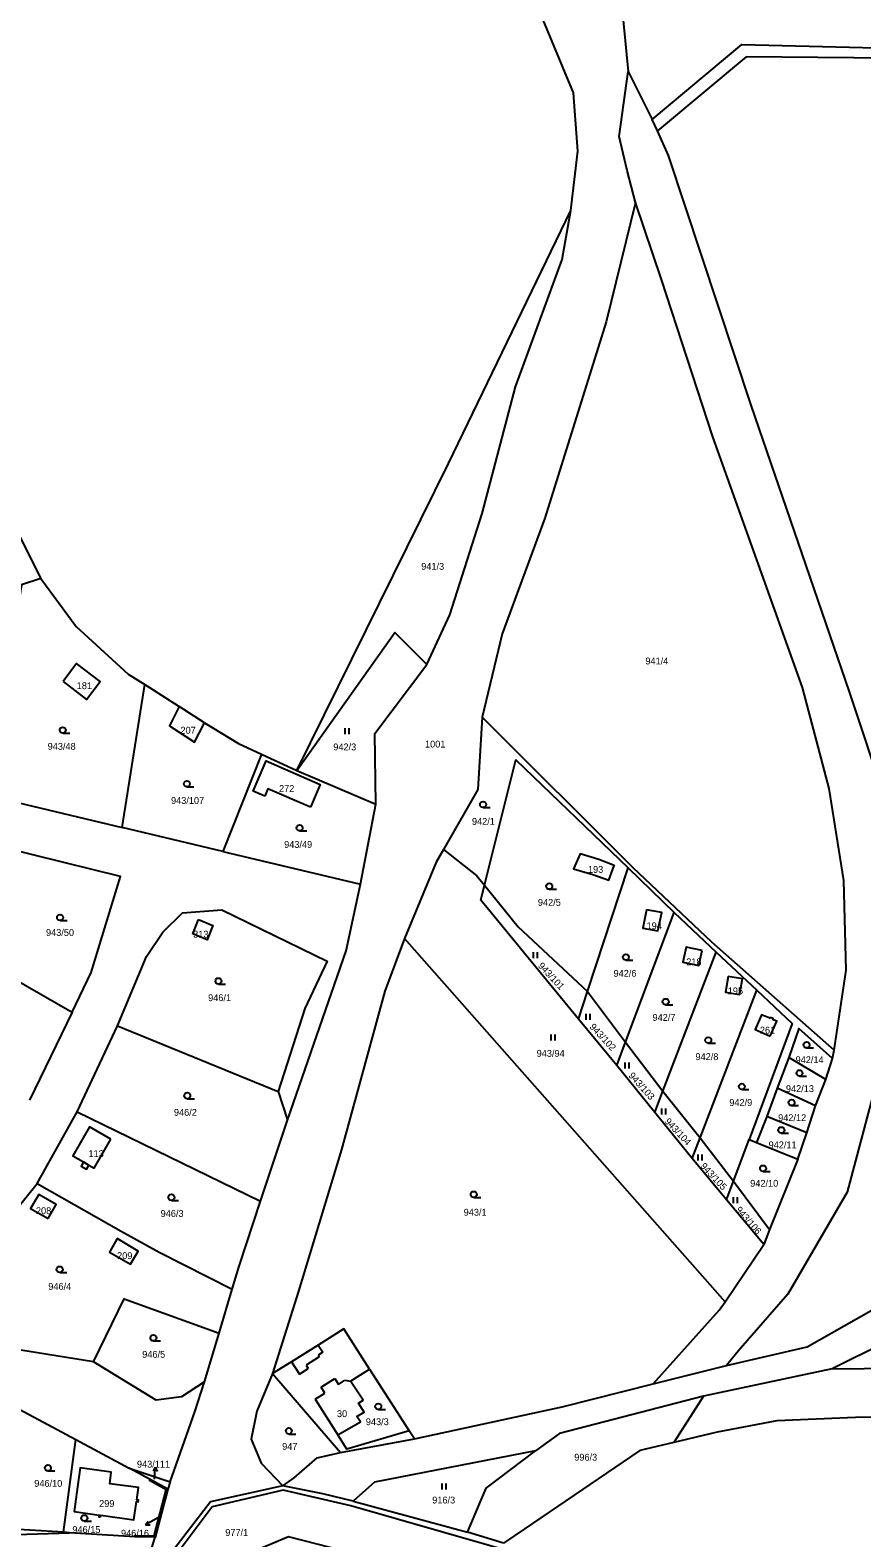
# Model space of a CAD drawing. Extents: x -7483133 to -743907, y -11317770 to -1129777.
# Drawn here: x -750645.6 to -750439.3, y -1131231.7 to -1130857.7 of the extents above; entities that cross this region are included whole.
import ezdxf

# ---------------------------------------------------------------- set-up
doc = ezdxf.new("R2010")
doc.units = 0
for name, color, linetype in [('Hranice parcel', 7, 'Continuous'), ('Parcelní čísla', 7, 'Continuous'), ('Pop  PČ popisy', 7, 'Continuous'), ('Vnitřní kresba', 7, 'Continuous'), ('Značky kultur', 7, 'Continuous')]:
    doc.layers.add(name, color=color, linetype=linetype)

msp = doc.modelspace()

# ---------------------------------------------------------------- linework, layer by layer
at = {"layer": 'Hranice parcel'}
for p, q in [((-750497.26, -1130867.97), (-750491.25, -1130879.86)), ((-750489.98, -1130882.7), (-750491.25, -1130879.86)), ((-750653.79, -1130972.43), (-750642.94, -1130993.73)), ((-750622.78, -1131055.54), (-750617.17, -1131020.08)), ((-750617.17, -1131020.08), (-750608.62, -1131025.49)), ((-750602.38, -1131029.51), (-750608.62, -1131025.49)), ((-750588.24, -1131037.32), (-750597.78, -1131061.49)), ((-750588.24, -1131037.32), (-750579.43, -1131041.4)), ((-750579.43, -1131041.4), (-750559.85, -1131049.76)), ((-750563.69, -1131069.55), (-750559.85, -1131049.76)), ((-750597.78, -1131061.49), (-750622.78, -1131055.54)), ((-750597.78, -1131061.49), (-750563.69, -1131069.55)), ((-750507.32, -1131096.22), (-750497.27, -1131065.52)), ((-750497.27, -1131065.52), (-750485.87, -1131076.56)), ((-750497.91, -1131108.74), (-750485.87, -1131076.56)), ((-750485.87, -1131076.56), (-750475.37, -1131086.44)), ((-750473.19, -1131173.15), (-750552.77, -1131083.07)), ((-750658.73, -1131087.82), (-750635.2, -1131101.36)), ((-750488.61, -1131120.96), (-750475.37, -1131086.44)), ((-750475.37, -1131086.44), (-750465.29, -1131095.85)), ((-750509.57, -1131103.09), (-750507.32, -1131096.22)), ((-750507.32, -1131096.22), (-750497.91, -1131108.74)), ((-750479.38, -1131132.47), (-750465.29, -1131095.85)), ((-750635.2, -1131101.36), (-750645.75, -1131123.19)), ((-750633.92, -1131126.08), (-750623.98, -1131104.75)), ((-750623.98, -1131104.75), (-750584.08, -1131121.02)), ((-750500.08, -1131114.54), (-750509.57, -1131103.09)), ((-750500.08, -1131114.54), (-750497.91, -1131108.74)), ((-750497.91, -1131108.74), (-750488.61, -1131120.96)), ((-750457.41, -1131112.56), (-750460.24, -1131120.18)), ((-750448.23, -1131118.01), (-750457.41, -1131112.56)), ((-750448.23, -1131118.01), (-750446.53, -1131112.81)), ((-750446.53, -1131112.81), (-750446.13, -1131110.72)), ((-750490.63, -1131126.23), (-750500.08, -1131114.54)), ((-750584.08, -1131121.02), (-750581.77, -1131128.11)), ((-750490.63, -1131126.23), (-750488.61, -1131120.96)), ((-750488.61, -1131120.96), (-750479.38, -1131132.47)), ((-750460.24, -1131120.18), (-750462.82, -1131127.24)), ((-750450.77, -1131124.56), (-750460.24, -1131120.18)), ((-750450.77, -1131124.56), (-750448.23, -1131118.01)), ((-750452.87, -1131131.28), (-750450.77, -1131124.56)), ((-750643.85, -1131143.83), (-750633.92, -1131126.08)), ((-750633.92, -1131126.08), (-750588.48, -1131148.2)), ((-750588.48, -1131148.2), (-750581.77, -1131128.11)), ((-750481.37, -1131137.63), (-750490.63, -1131126.23)), ((-750462.82, -1131127.24), (-750465.37, -1131133.64)), ((-750452.87, -1131131.28), (-750462.82, -1131127.24)), ((-750481.37, -1131137.63), (-750479.38, -1131132.47)), ((-750479.38, -1131132.47), (-750471.07, -1131143.22)), ((-750455.14, -1131137.79), (-750452.87, -1131131.28)), ((-750471.07, -1131143.22), (-750467.23, -1131132.9)), ((-750467.23, -1131132.9), (-750465.37, -1131133.64)), ((-750465.37, -1131133.64), (-750455.14, -1131137.79)), ((-750472.81, -1131147.91), (-750481.37, -1131137.63)), ((-750455.14, -1131137.79), (-750462.15, -1131155.21)), ((-750472.81, -1131147.91), (-750471.07, -1131143.22)), ((-750471.07, -1131143.22), (-750462.15, -1131155.21)), ((-750463.62, -1131158.93), (-750472.81, -1131147.91)), ((-750473.19, -1131173.15), (-750463.62, -1131158.93)), ((-750598.74, -1131180.95), (-750595.5, -1131170.04)), ((-750602.36, -1131193.01), (-750598.74, -1131180.95)), ((-750580.75, -1131188.08), (-750585.52, -1131190.95)), ((-750446.64, -1131189.81), (-750338.88, -1131188.45)), ((-750663.9, -1131191.45), (-750634.31, -1131207.35)), ((-750585.52, -1131190.95), (-750568.64, -1131210.54)), ((-750566.12, -1131192.88), (-750561.42, -1131189.86)), ((-750561.42, -1131189.86), (-750551.57, -1131205.21)), ((-750491, -1131193.51), (-750472.83, -1131188.97)), ((-750446.64, -1131189.81), (-750478.58, -1131196.61)), ((-750478.58, -1131196.61), (-750485.93, -1131208.1)), ((-750637.34, -1131230.32), (-750634.31, -1131207.35)), ((-750634.31, -1131207.35), (-750621.05, -1131214.47)), ((-750568.64, -1131210.54), (-750550.24, -1131207.13)), ((-750550.24, -1131207.13), (-750551.57, -1131205.21)), ((-750615.88, -1131217.25), (-750621.05, -1131214.47)), ((-750621.05, -1131214.47), (-750610.86, -1131217.83)), ((-750611.5, -1131219.65), (-750615.88, -1131217.25)), ((-750610.86, -1131217.83), (-750611.5, -1131219.65)), ((-750611.5, -1131219.65), (-750614.64, -1131231.58)), ((-750565.51, -1131222.62), (-750537.12, -1131230.36)), ((-750637.34, -1131230.32), (-750676.72, -1131228.08)), ((-750635.87, -1131230.45), (-750637.34, -1131230.32)), ((-750619.64, -1131231.48), (-750635.87, -1131230.45)), ((-750614.64, -1131231.58), (-750619.64, -1131231.48)), ((-750617.63, -1131241.09), (-750614.64, -1131231.58)), ((-750528.14, -1131233.04), (-750537.12, -1131230.36))]:
    msp.add_line(p, q, dxfattribs=at)
for points in [[(-750522.68, -1130780.11), (-750499.63, -1130847.01), (-750499.12, -1130848.49), (-750497.26, -1130867.97)], [(-750511.43, -1130902.47), (-750509.76, -1130887.71), (-750510.81, -1130873.25), (-750518.73, -1130854.13), (-750534.78, -1130807.35), (-750542.51, -1130784.25)], [(-750491.25, -1130879.86), (-750469.04, -1130861.3), (-750429.04, -1130862.24), (-750367.95, -1130862.53), (-750316.54, -1130862.71), (-750303.39, -1130867.71), (-750272.3, -1130886.08), (-750242.29, -1130900.85), (-750215.89, -1130913.25), (-750197.91, -1130920.02), (-750183.56, -1130928.08)], [(-750423.45, -1130864.72), (-750467.96, -1130864.31), (-750489.98, -1130882.7)], [(-750495.43, -1130900.48), (-750497.49, -1130892.54), (-750499.47, -1130884.13), (-750497.26, -1130867.97)], [(-750383.69, -1131147.48), (-750402.83, -1131122.9), (-750410.73, -1131109.04), (-750424.07, -1131076.84), (-750442.36, -1131021.87), (-750466.73, -1130950.73), (-750487.24, -1130888.84), (-750489.98, -1130882.7)], [(-750495.43, -1130900.48), (-750502.66, -1130930.1), (-750517.9, -1130978.8), (-750528.5, -1131007.43), (-750533.48, -1131028.12)], [(-750446.13, -1131110.72), (-750443.13, -1131090.87), (-750443.7, -1131068.64), (-750447.41, -1131045.86), (-750453.97, -1131020.75), (-750476.26, -1130958.59), (-750488.96, -1130919.57), (-750495.43, -1130900.48)], [(-750579.43, -1131041.4), (-750541.82, -1130965.24), (-750511.43, -1130902.47)], [(-750547.16, -1131015.06), (-750541.48, -1131002.77), (-750533.47, -1130977.66), (-750525.19, -1130946.2), (-750513.6, -1130914.64), (-750511.43, -1130902.47)], [(-750642.94, -1130993.73), (-750647.77, -1130995.31), (-750656.09, -1131047.61), (-750622.78, -1131055.54)], [(-750642.94, -1130993.73), (-750634.22, -1131005.62), (-750621.28, -1131017.48), (-750617.17, -1131020.08)], [(-750579.43, -1131041.4), (-750555.12, -1131007.18), (-750547.16, -1131015.06)], [(-750637.46, -1131019.3), (-750631.68, -1131023.76), (-750628.24, -1131019.3), (-750634.13, -1131014.8), (-750637.46, -1131019.3)], [(-750559.85, -1131049.76), (-750560.14, -1131032.23), (-750547.16, -1131015.06)], [(-750608.62, -1131025.49), (-750611.05, -1131030.29), (-750604.82, -1131034.31), (-750602.38, -1131029.51)], [(-750602.38, -1131029.51), (-750593.96, -1131034.68), (-750588.24, -1131037.32)], [(-750533.48, -1131028.12), (-750534.57, -1131046.11), (-750543.09, -1131060.97)], [(-750533.48, -1131028.12), (-750496.07, -1131065.4), (-750476.55, -1131083.89), (-750446.13, -1131110.72)], [(-750587.42, -1131047.77), (-750590.31, -1131046.51), (-750587.05, -1131039), (-750573.69, -1131044.84), (-750576.08, -1131050.47)], [(-750532.86, -1131069.86), (-750525.13, -1131038.7), (-750497.27, -1131065.52)], [(-750576.08, -1131050.47), (-750586.62, -1131045.94), (-750587.42, -1131047.77)], [(-750635.2, -1131101.36), (-750630.48, -1131091.47), (-750623.21, -1131067.69), (-750651.64, -1131060.63)], [(-750543.09, -1131060.97), (-750544.92, -1131064.15), (-750552.77, -1131083.07)], [(-750543.09, -1131060.97), (-750534.76, -1131067.51), (-750532.86, -1131069.86)], [(-750504.56, -1131063.49), (-750509.16, -1131062.02), (-750510.79, -1131065.79), (-750506.01, -1131067.14), (-750502.06, -1131068.59), (-750500.68, -1131064.97), (-750504.56, -1131063.49)], [(-750581.77, -1131128.11), (-750567.23, -1131086.09), (-750563.69, -1131069.55)], [(-750509.57, -1131103.09), (-750533.78, -1131073.55), (-750532.86, -1131069.86)], [(-750532.86, -1131069.86), (-750524.54, -1131080.18), (-750507.32, -1131096.22)], [(-750623.98, -1131104.75), (-750616.75, -1131087.54), (-750612.73, -1131081.49), (-750607.8, -1131076.65), (-750598.04, -1131075.93), (-750571.89, -1131088.67), (-750577.49, -1131100.38), (-750584.08, -1131121.02)], [(-750492.72, -1131075.93), (-750493.64, -1131080.46), (-750489.87, -1131081.14), (-750488.93, -1131076.61), (-750492.72, -1131075.93)], [(-750603.83, -1131078.3), (-750600.26, -1131079.81), (-750601.72, -1131083.35), (-750605.26, -1131081.88), (-750603.83, -1131078.3)], [(-750552.77, -1131083.07), (-750557.65, -1131096.13), (-750568.36, -1131135.43), (-750579.01, -1131170.54), (-750585.52, -1131190.95)], [(-750478.89, -1131086.02), (-750482.83, -1131085.21), (-750483.68, -1131088.93), (-750479.74, -1131089.74), (-750478.89, -1131086.02)], [(-750472.41, -1131092.46), (-750473.07, -1131096.33), (-750469.61, -1131096.96), (-750468.91, -1131093.02), (-750472.41, -1131092.46)], [(-750465.29, -1131095.85), (-750456.53, -1131104.12), (-750467.23, -1131132.9)], [(-750461.4, -1131103.14), (-750461.28, -1131102.87), (-750461.99, -1131102.61), (-750462.09, -1131102.85), (-750464.13, -1131101.99), (-750465.72, -1131105.65), (-750461.99, -1131107.27)], [(-750461.99, -1131107.27), (-750460.34, -1131103.59), (-750461.4, -1131103.14)], [(-750446.53, -1131112.81), (-750454.86, -1131105.37), (-750457.41, -1131112.56)], [(-750398.36, -1131153.41), (-750414.23, -1131134.96), (-750424.36, -1131119.49), (-750435.97, -1131119.86), (-750442.91, -1131145.97), (-750457.63, -1131171.27), (-750469.94, -1131185.39), (-750472.83, -1131188.97)], [(-750625.57, -1131132.81), (-750630.88, -1131129.76), (-750635.02, -1131136.97), (-750632.39, -1131138.48), (-750632.98, -1131139.52), (-750631.64, -1131140.29), (-750631.05, -1131139.25), (-750629.72, -1131140.04), (-750625.57, -1131132.81)], [(-750629.89, -1131188.07), (-750647.96, -1131185.17), (-750660.39, -1131170.67), (-750661.43, -1131165.52), (-750643.85, -1131143.83)], [(-750643.85, -1131143.83), (-750623.08, -1131155.63), (-750613.63, -1131160.87), (-750595.5, -1131170.04)], [(-750641.17, -1131152.51), (-750639.14, -1131149.06), (-750643.44, -1131146.53), (-750645.5, -1131150.03), (-750641.17, -1131152.51)], [(-750595.5, -1131170.04), (-750593.76, -1131164.33), (-750588.48, -1131148.2)], [(-750472.83, -1131188.97), (-750452.8, -1131184.37), (-750398.36, -1131153.41)], [(-750462.15, -1131155.21), (-750463.19, -1131157.85), (-750463.62, -1131158.93)], [(-750624.01, -1131157.51), (-750625.92, -1131160.82), (-750620.73, -1131163.85), (-750618.82, -1131160.58), (-750624.01, -1131157.51)], [(-750384.23, -1131161.42), (-750394.55, -1131163.95), (-750446.64, -1131189.81)], [(-750629.89, -1131188.07), (-750622.31, -1131172.46), (-750598.74, -1131180.95)], [(-750491, -1131193.51), (-750474.63, -1131175.29), (-750473.19, -1131173.15)], [(-750561.42, -1131189.86), (-750567.81, -1131179.9), (-750574.13, -1131183.9), (-750580.75, -1131188.08)], [(-750602.36, -1131193.01), (-750608.11, -1131196.71), (-750614.32, -1131197.54), (-750629.89, -1131188.07)], [(-750585.52, -1131190.95), (-750589.37, -1131200.29), (-750590.81, -1131207.27), (-750588.28, -1131213.22), (-750582.93, -1131218.86)], [(-750610.86, -1131217.83), (-750604.75, -1131200.5), (-750602.36, -1131193.01)], [(-750551.57, -1131205.21), (-750567.07, -1131209.71), (-750569.3, -1131206.19), (-750563.67, -1131202.94), (-750564.53, -1131201.59), (-750562.76, -1131200.55), (-750564.16, -1131198.33), (-750562.99, -1131197.56), (-750566.12, -1131192.88)], [(-750550.24, -1131207.13), (-750513.65, -1131199.22), (-750491, -1131193.51)], [(-750478.58, -1131196.61), (-750514.29, -1131205.87), (-750520.23, -1131210.17)], [(-750324.56, -1131199.94), (-750440.85, -1131201.86), (-750460.37, -1131202.74), (-750475.17, -1131205.54), (-750485.93, -1131208.1)], [(-750582.93, -1131218.86), (-750580.15, -1131216.88), (-750574.41, -1131211.88), (-750568.64, -1131210.54)], [(-750520.23, -1131210.17), (-750560.2, -1131217.92), (-750565.51, -1131222.62)], [(-750537.12, -1131230.36), (-750535.86, -1131227.39), (-750535.03, -1131225.44), (-750532.48, -1131219.42), (-750520.23, -1131210.17)], [(-750485.93, -1131208.1), (-750494.34, -1131210.1), (-750520.95, -1131228.16), (-750523.07, -1131229.6), (-750528.14, -1131233.04)], [(-750628.17, -1131226.54), (-750628.11, -1131226.14), (-750619.86, -1131227.28), (-750619.23, -1131222.73), (-750618.83, -1131222.78), (-750618.78, -1131222.38), (-750619.17, -1131222.33), (-750618.75, -1131219.27), (-750625.88, -1131218.29), (-750625.49, -1131215.43), (-750633.21, -1131214.37), (-750633.6, -1131217.22), (-750634.7, -1131225.23), (-750628.5, -1131226.09), (-750628.56, -1131226.48), (-750628.17, -1131226.54)], [(-750619.64, -1131231.48), (-750619.63, -1131231.18), (-750614.87, -1131231.27), (-750611.85, -1131219.8), (-750616.03, -1131217.51), (-750615.88, -1131217.25)], [(-750582.93, -1131218.86), (-750600.91, -1131222.79), (-750618.46, -1131245.66)], [(-750565.51, -1131222.62), (-750573.02, -1131220.81), (-750582.93, -1131218.86)], [(-750818.16, -1131224.81), (-750709.78, -1131231), (-750659.74, -1131231.2), (-750635.87, -1131230.45)]]:
    msp.add_lwpolyline(points, dxfattribs=at)
at = {"layer": 'Pop  PČ popisy'}
for p, q in [((-750614.58, -1131214.2), (-750615.14, -1131215.18)), ((-750614.74, -1131217.2), (-750614.58, -1131214.2)), ((-750614.58, -1131214.2), (-750614.14, -1131215.23)), ((-750614.38, -1131227.04), (-750616.98, -1131228.54)), ((-750616.98, -1131228.54), (-750616.36, -1131227.61)), ((-750616.98, -1131228.54), (-750615.86, -1131228.47)), ((-750613.36, -1131226.46), (-750614.38, -1131227.04))]:
    msp.add_line(p, q, dxfattribs=at)
at = {"layer": 'Vnitřní kresba'}
for p, q in [((-750632.39, -1131138.48), (-750631.05, -1131139.25)), ((-750574.13, -1131183.9), (-750573.01, -1131185.68)), ((-750580.75, -1131188.08), (-750578.82, -1131191.13)), ((-750573.93, -1131186.85), (-750577.15, -1131188.89)), ((-750577.15, -1131188.89), (-750576.61, -1131189.74)), ((-750573.01, -1131185.68), (-750574.2, -1131186.43)), ((-750574.2, -1131186.43), (-750573.93, -1131186.85)), ((-750578.82, -1131191.13), (-750576.61, -1131189.74)), ((-750573.44, -1131194.38), (-750570.05, -1131192.24)), ((-750570.05, -1131192.24), (-750569.14, -1131193.68)), ((-750569.14, -1131193.68), (-750567.53, -1131192.65)), ((-750567.53, -1131192.65), (-750566.12, -1131192.88)), ((-750574.9, -1131197.33), (-750572.53, -1131195.82)), ((-750572.53, -1131195.82), (-750573.44, -1131194.38)), ((-750574.9, -1131197.33), (-750569.3, -1131206.19)), ((-750582.84, -1131219.92), (-750600.48, -1131224.07)), ((-750566.04, -1131223.81), (-750582.84, -1131219.92)), ((-750600.48, -1131224.07), (-750617.99, -1131247.26)), ((-750506.88, -1131240.71), (-750566.04, -1131223.81)), ((-750581.51, -1131231.45), (-750591.91, -1131235.86)), ((-750553.71, -1131238.62), (-750581.51, -1131231.45))]:
    msp.add_line(p, q, dxfattribs=at)
at = {"layer": 'Značky kultur'}
for p, q in [((-750567.48, -1131032.38), (-750567.48, -1131030.88)), ((-750566.48, -1131032.38), (-750566.48, -1131030.88)), ((-750637.53, -1131032.11), (-750635.78, -1131032.11)), ((-750606.74, -1131045.43), (-750604.99, -1131045.43)), ((-750533.24, -1131050.56), (-750531.49, -1131050.56)), ((-750578.76, -1131056.35), (-750577.01, -1131056.35)), ((-750516.81, -1131070.83), (-750515.06, -1131070.83)), ((-750638.2, -1131078.59), (-750636.45, -1131078.59)), ((-750520.73, -1131087.95), (-750520.73, -1131086.45)), ((-750519.73, -1131087.95), (-750519.73, -1131086.45)), ((-750497.81, -1131088.44), (-750496.06, -1131088.44)), ((-750598.9, -1131094.36), (-750597.15, -1131094.36)), ((-750507.64, -1131103.22), (-750507.64, -1131101.72)), ((-750506.64, -1131103.22), (-750506.64, -1131101.72)), ((-750487.94, -1131099.49), (-750486.19, -1131099.49)), ((-750516.34, -1131108.35), (-750516.34, -1131106.85)), ((-750515.34, -1131108.35), (-750515.34, -1131106.85)), ((-750477.36, -1131109.02), (-750475.61, -1131109.02)), ((-750452.97, -1131110.19), (-750451.22, -1131110.19)), ((-750498, -1131115.31), (-750498, -1131113.81)), ((-750497, -1131115.31), (-750497, -1131113.81)), ((-750454.73, -1131117.19), (-750452.98, -1131117.19)), ((-750469.04, -1131120.52), (-750467.29, -1131120.52)), ((-750606.63, -1131122.79), (-750604.88, -1131122.79)), ((-750488.87, -1131126.72), (-750488.87, -1131125.22)), ((-750487.87, -1131126.72), (-750487.87, -1131125.22)), ((-750456.69, -1131124.51), (-750454.94, -1131124.51)), ((-750459.24, -1131131.32), (-750457.49, -1131131.32)), ((-750479.89, -1131138.1), (-750479.89, -1131136.6)), ((-750478.89, -1131138.1), (-750478.89, -1131136.6)), ((-750463.76, -1131140.83), (-750462.01, -1131140.83)), ((-750535.56, -1131147.27), (-750533.81, -1131147.27)), ((-750471.09, -1131148.71), (-750471.09, -1131147.21)), ((-750470.09, -1131148.71), (-750470.09, -1131147.21)), ((-750610.58, -1131148.01), (-750608.83, -1131148.01)), ((-750638.3, -1131165.89), (-750636.55, -1131165.89)), ((-750615.05, -1131182.89), (-750613.3, -1131182.89)), ((-750559.24, -1131199.89), (-750557.49, -1131199.89)), ((-750581.44, -1131205.97), (-750579.69, -1131205.97)), ((-750641.21, -1131215.14), (-750639.46, -1131215.14)), ((-750543.36, -1131219.73), (-750543.36, -1131218.23)), ((-750542.36, -1131219.73), (-750542.36, -1131218.23)), ((-750632.18, -1131227.57), (-750630.43, -1131227.57))]:
    msp.add_line(p, q, dxfattribs=at)
for centre in [(-750637.53, -1131031.36), (-750606.74, -1131044.68), (-750533.24, -1131049.81), (-750578.76, -1131055.6), (-750516.81, -1131070.08), (-750638.2, -1131077.84), (-750497.81, -1131087.69), (-750598.9, -1131093.61), (-750487.94, -1131098.74), (-750477.36, -1131108.27), (-750452.97, -1131109.44), (-750454.73, -1131116.44), (-750606.63, -1131122.04), (-750469.04, -1131119.77), (-750456.69, -1131123.76), (-750459.24, -1131130.57), (-750463.76, -1131140.08), (-750610.58, -1131147.26), (-750535.56, -1131146.52), (-750638.3, -1131165.14), (-750615.05, -1131182.14), (-750559.24, -1131199.14), (-750581.44, -1131205.22), (-750641.21, -1131214.39), (-750632.18, -1131226.82)]:
    msp.add_circle(centre, 0.75, dxfattribs=at)

# ---------------------------------------------------------------- texts
at = {"layer": 'Parcelní čísla'}
for s, p in [('941/3', (-750548.59, -1130991.58)), ('941/4', (-750492.97, -1131015.06)), ('181', (-750634.07, -1131021.19)), ('207', (-750608.33, -1131032.23)), ('943/48', (-750641.28, -1131036.23)), ('942/3', (-750570.41, -1131036.38)), ('1001', (-750547.65, -1131035.67)), ('272', (-750583.87, -1131046.69)), ('943/107', (-750610.67, -1131049.66)), ('942/1', (-750536, -1131054.85)), ('943/49', (-750582.6, -1131060.57)), ('193', (-750507.22, -1131066.76)), ('942/5', (-750519.64, -1131074.94)), ('194', (-750492.68, -1131080.75)), ('943/50', (-750641.69, -1131082.41)), ('313', (-750605.18, -1131082.83)), ('942/6', (-750500.87, -1131092.54)), ('218', (-750482.83, -1131089.69)), ('195', (-750472.54, -1131096.9)), ('946/1', (-750601.46, -1131098.59)), ('942/7', (-750491.2, -1131103.48)), ('261', (-750464.56, -1131106.64)), ('943/94', (-750519.95, -1131112.39)), ('942/8', (-750480.54, -1131113.21)), ('942/14', (-750455.7, -1131113.97)), ('942/13', (-750458.1, -1131121.15)), ('946/2', (-750609.95, -1131127.03)), ('942/9', (-750472.15, -1131124.59)), ('942/12', (-750460.03, -1131128.36)), ('113', (-750631.15, -1131137.27)), ('942/11', (-750462.4, -1131135.09)), ('942/10', (-750466.96, -1131144.63)), ('208', (-750644.19, -1131151.43)), ('946/3', (-750613.25, -1131152.11)), ('943/1', (-750538.06, -1131151.81)), ('209', (-750624.05, -1131162.58)), ('946/4', (-750641.12, -1131170.21)), ('946/5', (-750617.81, -1131187.06)), ('30', (-750569.5, -1131201.78)), ('943/3', (-750562.33, -1131203.77)), ('947', (-750583.1, -1131209.91)), ('996/3', (-750510.62, -1131212.58)), ('943/111', (-750619.13, -1131214.31)), ('946/10', (-750644.6, -1131219.07)), ('299', (-750628.51, -1131224.06)), ('916/3', (-750545.86, -1131223.2)), ('946/15', (-750635.15, -1131230.52)), ('946/16', (-750623.08, -1131231.44)), ('977/1', (-750597.21, -1131231.25))]:
    msp.add_text(s, height=1.7, dxfattribs=at).set_placement(p)
for s, rotation, p in [('943/101', 313, (-750519.74, -1131089.93)), ('943/102', 313, (-750506.94, -1131105.09)), ('943/103', 312, (-750497.27, -1131117.16)), ('943/104', 313, (-750488.3, -1131128.54)), ('943/105', 313, (-750479.44, -1131139.64)), ('943/106', 311, (-750470.69, -1131150.44))]:
    msp.add_text(s, height=1.7, rotation=rotation, dxfattribs=at).set_placement(p)

doc.saveas('drawing.dxf')
